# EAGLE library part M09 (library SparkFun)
Header 9 Standard 9-pin 0.1" header. Use with straight break away headers (SKU : PType-HD), right angle break away headers (PType-HD-RightAngle), swiss pins (PType-30F), machine pins (PType-MP), and female headers (PType-FH). Molex polarized connector foot print use with SKU : Con-Hdr with associated crimp pins and housings.
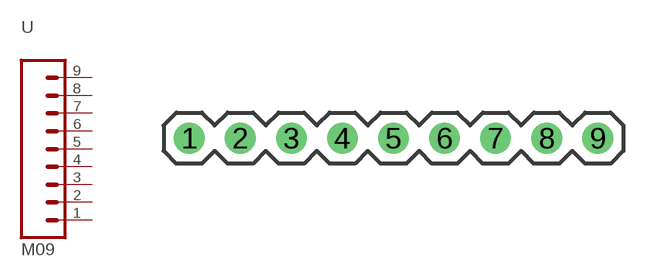
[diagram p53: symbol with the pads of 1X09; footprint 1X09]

Designator prefix -

## M09  [1X09]
1  1  pas
2  2  pas
3  3  pas
4  4  pas
5  5  pas
6  6  pas
7  7  pas
8  8  pas
9  9  pas

## Footprint 1X09 (pad centres in mm)
drill 1.016 round: 1 0,0; 2 2.54,0; 3 5.08,0; 4 7.62,0; 5 10.16,0; 6 12.7,0; 7 15.24,0; 8 17.78,0; 9 20.32,0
